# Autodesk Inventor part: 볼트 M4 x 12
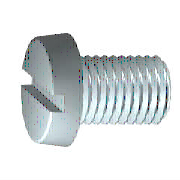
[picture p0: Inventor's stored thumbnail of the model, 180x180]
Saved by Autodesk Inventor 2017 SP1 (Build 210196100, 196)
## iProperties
Created: 2012-02
Part Number: 볼트 M4 x 12
Material: 강철, 연강
Description: 6각머리 태핑 나사
Document SubType Name: Modeling
Standard: KS B 1021
Designer: mduedu
Standards Organization: KS
Language: ko-KR
Size Designation: A  M 4 x 12
Categories: <MemberInstance><Categories><Category DisplayName="조임쇠" InternalName="e4da775c-781d-43d5-af7c-5136215cf5a6" Mnemonic="FSTN"><Category DisplayName="볼트" InternalN
Density: 1 g/cm^3
Appearance: 강철
IsCustomPart: 0
Author: mduedu
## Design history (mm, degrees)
body "Solid1"
revolve "본체" stored, may be unused: angle "d8" = 90 deg
sketch "스케치2"
  geometry: L1 (0, 0)-(0, 3.273) reference; L2 (-3.5, 0.6)-(3.5, 0.6); L3 (3.5, 0.6)-(3.5, -0.6); L4 (3.5, -0.6)-(-3.5, -0.6); L5 (-3.5, -0.6)-(-3.5, 0.6); L6 (-3.5, 0)-(3.5, 0); L7 (0, 0.6)-(0, -0.6); C1 r 3.5 at (0, 0) reference; 1 further point
  constraints: 12 end point, 5 midpoint, 2 parallel, 1 collinear, 1 horizontal, 1 perpendicular
  dimensions: "d11" = 1.2 distance of L4.end L2.start (= SBR); "d12" = 7 distance of L2.start L2.end (= KOD)
fillet "모깎기1" dims "d14" = 0.2 (= RR)
extrude "슬롯" cut sketch "스케치2" distance "d19" = 1.1 (= STI); taper "d20" = 0 deg
feature "스레드" dims "d15" = 10.6 (= GEL), "d16" = 0
chamfer "모따기1" distance "d17" = 0.42941 (= -0.5 x SPD + 0.5 x GD); stored, may be unused: second distance "d18" = 0.42952 (computed from GUL), angle "d36" = 45 deg
workplane "Work Plane1"
sketch "스케치1"
  geometry: L1 (-2.6, 0)-(12, 0); L2 (12, 0)-(12, 2); L3 (12, 2)-(1.4, 2); L4 (1.4, 2)-(0.97, 1.785); L5 (0.97, 1.785)-(0, 1.785); L6 (0, 1.785)-(0, 3.5); L7 (-5.52, 0)-(14.92, 0) reference; L8 (0, -0.7)-(0, 4.2) reference; L9 (-2.6, 0)-(-2.6, 3.273); L10 (0, 3.5)-(-2.6, 3.273); L11 (1.4, 2)-(0, 2)
  constraints: 18 end point, 4 parallel, 2 collinear, 2 perpendicular, 1 horizontal, 1 point on line
  dimensions: "d0" = 12 distance between parallel lines of L2 L6 (= NLG); "d1" = 10.6 distance from line of L3.end L2 (= GEL); "d2" = 0.42952 horizontal distance of L4.end L3.end (computed from GAL); "d3" = 2.6 distance from line of L1.start L6 (= KOH); "d4" = 4 diameter of L3 L1 (= GD); "d5" = 3.5705 diameter of L5 L1 (= BDM); "d9" = 7 diameter of L6.end L1 (= KOD); "d10" = 5 deg angle of L10 L1 (= KEWI)
other parameters: "GD" = 4 (= NND) [user parameter; used in 2 equation terms], "NLG" = 12 [user parameter; used in 1 equation term], "GEL" = 10.6 [user parameter; used in 2 equation terms], "KOD" = 7 [user parameter; used in 2 equation terms], "KOH" = 2.6 [user parameter; used in 1 equation term], "GAL" = 0.42941 (= 0.61345 x PTC) [user parameter; used in 1 equation term], "SPD" = 3.14117 (= NND - 1.2269 x PTC) [user parameter; used in 1 equation term], "BDM" = 3.5705 [user parameter; used in 1 equation term], "GUL" = 0.42941 (= 0.61345 x PTC) [user parameter; used in 1 equation term], "RR" = 0.2 [user parameter; used in 1 equation term], "d7" = 0, "SBR" = 1.2 [user parameter; used in 1 equation term], "STI" = 1.1 [user parameter; used in 1 equation term], "KEWI" = 5 deg [user parameter; used in 1 equation term], "d37" = 0, "d39" = 0, "PTC" = 0.7 [user parameter; used in 5 equation terms], "THREADDIA" = 4 [user parameter; used in 1 equation term], "TOA" = 30 deg [user parameter], "TPU" = 14.28571 (computed from PTC) [user parameter], "NND" = 4 [user parameter; used in 2 equation terms], "GD1" = 3.14117 (= THREADDIA - 1.2269 x PTC) [user parameter]
